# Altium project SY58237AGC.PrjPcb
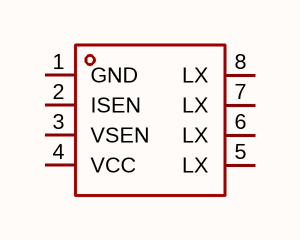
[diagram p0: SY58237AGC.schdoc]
1 sheet, 1 parts. Net scope: global (net labels, ports and power ports of the same name join across sheets).

## Sheet SY58237AGC.schdoc
size 127 x 101 mm

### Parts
U?  sy58237agc  [DIP-8_L9.3-W6.4-P2.54-LS7.6-BL]  (value not drawn)

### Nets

Not connected (* = marked no-connect by the designer): U? 1(GND) 2(ISEN) 3(VSEN) 4(VCC) 5(LX) 6(LX) 7(LX) 8(LX)

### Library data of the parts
U? = sy58237agc: 类型:-;工作电压(DC):-;开关频率:150kHz;通道数:1;输出电压:-;输出电流:-;调光:-;拓扑结构:反激;; Manufacturer: Silergy(矽力杰); AddInBom: yes; ModelId: e1ba2ac1384341a197ae27979c8d8942; ModelName: DIP-8_L9.3-W6.4-H4.5-P2.54-LS7.6-BL; ModelTransform: 364.173,311.8104,0,0,0,0,0,0,-118.11; Frequency - Switching: 150kHz; Number of Channels: 1; Topology: 反激; Switch Tube (Built-In/External): 内置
